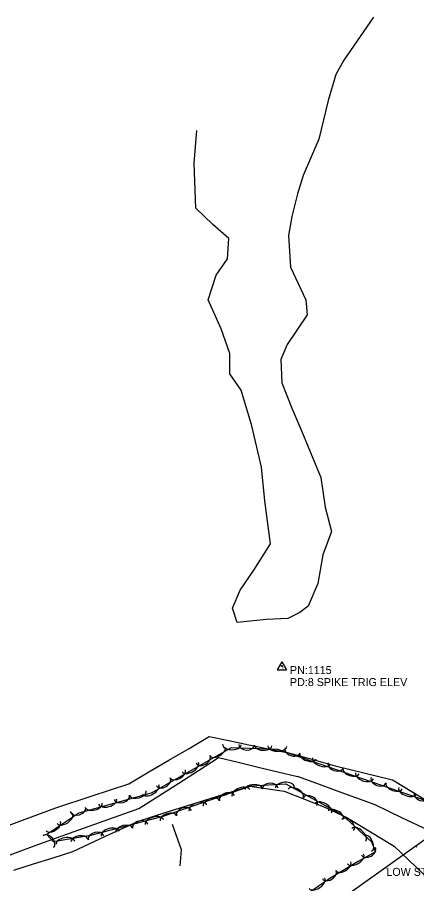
# Model space of a CAD drawing. Extents: x 1451369 to 1458940, y 1868647 to 1875095.
# Drawn here: x 1454031 to 1454280, y 1871459 to 1872000 of the extents above; entities that cross this region are included whole.
import ezdxf

# ---------------------------------------------------------------- set-up
doc = ezdxf.new("R2010")
doc.units = 0
for name, color, linetype in [('E_Existing_ROW', 7, 'Continuous'), ('E_Proposed ROW and Easements', 7, 'Continuous'), ('E_ROW Point Number', 7, 'Continuous'), ('E_Station Offset', 7, 'Continuous'), ('E_Tract Residual', 7, 'Continuous'), ('S_EXIST_ROW', 7, 'Continuous'), ('S_MISC_STRUCTURES_ANNOT', 7, 'Continuous'), ('S_SECONDARY_CTL_ANNOT', 7, 'Continuous')]:
    doc.layers.add(name, color=color, linetype=linetype)

msp = doc.modelspace()

# ---------------------------------------------------------------- linework, layer by layer
at = {"layer": 'E_Existing_ROW'}
msp.add_line((1454539.16, 1871667.36), (1454213.66, 1871435.13), dxfattribs=at)
at = {"layer": 'E_Proposed ROW and Easements'}
for points in [[(1454279.82, 1871481.69), (1454279.82, 1871481.74), (1454279.82, 1871481.69), (1454279.77, 1871481.69), (1454279.82, 1871481.69), (1454279.82, 1871481.64), (1454279.82, 1871481.69), (1454279.87, 1871481.69)], [(1454261.12, 1871468.48), (1454261.12, 1871468.53), (1454261.12, 1871468.48), (1454261.07, 1871468.48), (1454261.12, 1871468.48), (1454261.12, 1871468.43), (1454261.12, 1871468.48), (1454261.17, 1871468.48)]]:
    msp.add_lwpolyline(points, dxfattribs=at)
at = {"layer": 'E_ROW Point Number'}
msp.add_lwpolyline([(1454291.89, 1871508.3), (1454234.83, 1871528.11), (1454193.49, 1871542.37), (1454164.2, 1871543.4), (1454141.27, 1871530.42), (1454114.39, 1871515.17), (1454069.24, 1871502.63), (1454049.38, 1871489.36), (1454053.2, 1871485.02), (1454076.69, 1871488.85), (1454121.93, 1871500.68), (1454176.82, 1871519.68), (1454198.38, 1871520.85), (1454233.52, 1871501.66), (1454251.77, 1871484.69), (1454254.34, 1871478.55), (1454243.51, 1871472.47), (1454225.87, 1871461.79), (1454192.81, 1871439.12)], dxfattribs=at)
for centre, major_axis, ratio, start_param, end_param in [((1454155.79, 1871541.08), (4.65, 2.63), 0.540712, 3.141564, 6.283157), ((1454164.68, 1871545.5), (5.86, -0.21), 0.550067, 3.141587, 6.28318), ((1454173.94, 1871545.44), (4.95, -0.17), 0.685295, 3.141584, 6.283176), ((1454184.23, 1871544.82), (5.34, -0.19), 0.540687, 3.141587, 6.28318), ((1454193.09, 1871544.51), (5.86, -0.21), 0.550067, 3.141587, 6.28318), ((1454202.57, 1871541.76), (4.68, -1.62), 0.685295, 3.14157, 6.283163), ((1454146.7, 1871536.23), (4.31, 2.44), 0.685327, 3.141544, 6.283137), ((1454212.23, 1871538.15), (5.05, -1.74), 0.540687, 3.14158, 6.283172), ((1454220.61, 1871535.26), (5.55, -1.91), 0.550067, 3.141579, 6.283172), ((1454138.77, 1871531.44), (5.1, 2.9), 0.550074, 3.141593, 6.283185), ((1454229.45, 1871532.49), (4.68, -1.62), 0.685295, 3.14157, 6.283163), ((1454131.05, 1871527.07), (4.65, 2.64), 0.540694, 3.141593, 6.283185), ((1454239.1, 1871528.87), (5.05, -1.75), 0.540686, 3.141593, 6.283185), ((1454247.48, 1871525.97), (5.54, -1.92), 0.550066, 3.141593, 6.283185), ((1454114.04, 1871517.41), (5.1, 2.9), 0.550074, 3.141593, 6.283185), ((1454121.97, 1871522.21), (4.31, 2.45), 0.685304, 3.141593, 6.283185), ((1454178.29, 1871517.64), (-5.34, -0.29), 0.540688, 3.141593, 6.283185), ((1454188.59, 1871517.93), (-4.95, -0.27), 0.685296, 3.141593, 6.283185), ((1454197.82, 1871518.69), (-5.86, -0.32), 0.550068, 3.141593, 6.283185), ((1454256.31, 1871523.18), (4.68, -1.63), 0.685293, 3.141593, 6.283185), ((1454265.96, 1871519.55), (5.05, -1.75), 0.540686, 3.141593, 6.283185), ((1454106.05, 1871515.06), (5.15, 1.43), 0.54069, 3.141593, 6.283185), ((1454161.75, 1871511.95), (-4.68, -1.62), 0.6853, 3.141593, 6.283185), ((1454170.42, 1871515.22), (-5.55, -1.92), 0.550071, 3.141593, 6.283185), ((1454204.56, 1871515.06), (-4.69, 2.56), 0.540686, 3.141593, 6.283185), ((1454274.33, 1871516.64), (5.54, -1.92), 0.550066, 3.141593, 6.283185), ((1454283.17, 1871513.85), (4.68, -1.63), 0.685293, 3.141593, 6.283185), ((1454087.2, 1871509.82), (5.65, 1.57), 0.550071, 3.141593, 6.283185), ((1454096.06, 1871512.55), (4.77, 1.33), 0.685299, 3.141593, 6.283185), ((1454143.55, 1871505.92), (-5.55, -1.92), 0.550071, 3.141593, 6.283185), ((1454151.93, 1871508.82), (-5.05, -1.75), 0.540691, 3.141593, 6.283185), ((1454213.47, 1871509.89), (-4.35, 2.37), 0.685294, 3.141593, 6.283185), ((1454221.72, 1871505.69), (-5.15, 2.81), 0.550066, 3.141593, 6.283185), ((1454068.67, 1871504.94), (4.77, 1.33), 0.685299, 3.141593, 6.283185), ((1454078.66, 1871507.44), (5.15, 1.43), 0.54069, 3.141593, 6.283185), ((1454134.89, 1871502.64), (-4.68, -1.62), 0.6853, 3.141593, 6.283185), ((1454229.51, 1871501.44), (-4.69, 2.56), 0.540686, 3.141593, 6.283185), ((1454060.56, 1871499.38), (4.79, 3.2), 0.560424, 3.140937, 6.28253), ((1454116.39, 1871497.04), (-5.68, -1.48), 0.55007, 3.141593, 6.283185), ((1454125.07, 1871499.52), (-5.05, -1.75), 0.540691, 3.141593, 6.283185), ((1454236.94, 1871495.23), (-3.63, 3.37), 0.685296, 3.141593, 6.283185), ((1454053.32, 1871494.54), (4.36, 2.92), 0.550868, 3.140958, 6.282551), ((1454088.89, 1871489.85), (-5.68, -1.48), 0.55007, 3.141593, 6.283185), ((1454097.47, 1871492.09), (-5.17, -1.35), 0.54069, 3.141593, 6.283185), ((1454107.5, 1871494.44), (-4.79, -1.25), 0.685299, 3.141593, 6.283185), ((1454243.9, 1871489.11), (-4.3, 4), 0.550068, 3.141593, 6.283185), ((1454050.22, 1871484.8), (-3.22, 3.67), 0.695641, 3.143081, 6.284673), ((1454060.87, 1871484.12), (-5.79, -0.94), 0.550069, 3.141593, 6.283185), ((1454069.62, 1871485.55), (-5.28, -0.86), 0.540689, 3.141593, 6.283185), ((1454080, 1871487.25), (-4.79, -1.25), 0.685299, 3.141593, 6.283185), ((1454249.85, 1871483.78), (-2.07, 4.93), 0.540693, 3.141593, 6.283185), ((1454241.92, 1871473.98), (5.01, 3.03), 0.551082, 3.141802, 6.283395), ((1454249.91, 1871478.8), (4.32, 2.43), 0.685304, 3.141593, 6.283185), ((1454234.34, 1871469.4), (4.57, 2.76), 0.541684, 3.141795, 6.283388), ((1454225.41, 1871464.3), (4.23, 2.56), 0.686559, 3.141936, 6.283529), ((1454217.82, 1871458.85), (4.81, 3.3), 0.553457, 3.14195, 6.283543)]:
    msp.add_ellipse(centre, major_axis=major_axis, ratio=ratio, start_param=start_param, end_param=end_param, dxfattribs=at)
at = {"layer": 'E_Station Offset'}
for p, q in [((1454195.96, 1871597.1), (1454192.95, 1871592.15)), ((1454195.96, 1871597.1), (1454198.91, 1871592.15)), ((1454192.95, 1871592.15), (1454198.91, 1871592.15))]:
    msp.add_line(p, q, dxfattribs=at)
for radius in [0.311, 0.183, 0.103]:
    msp.add_circle((1454195.96, 1871594.49), radius, dxfattribs=at)
at = {"layer": 'E_Tract Residual'}
for points in [[(1454253.12, 1871999.62), (1454234.59, 1871972.88), (1454229.63, 1871963.93), (1454224.76, 1871947.65), (1454218.97, 1871923.45), (1454209.19, 1871900.79), (1454205.64, 1871889.48), (1454202.05, 1871875.28), (1454200.11, 1871863.38), (1454201.4, 1871843.58), (1454210.85, 1871823.15), (1454211.64, 1871813.77), (1454199.26, 1871795.26), (1454195.19, 1871785.93), (1454195.83, 1871771.37), (1454202.09, 1871755.49), (1454208.36, 1871740.9), (1454220.19, 1871712.18), (1454222.91, 1871693.64), (1454226.84, 1871678.47), (1454221.39, 1871663.94), (1454218.42, 1871646.14), (1454212.29, 1871631.88), (1454207.1, 1871628.03), (1454199.56, 1871624.12), (1454186.36, 1871623.52), (1454168.09, 1871621.61), (1454165.18, 1871630.74), (1454169.92, 1871641.86), (1454178.49, 1871654.37), (1454188.83, 1871670.88), (1454185.34, 1871697.6), (1454183.15, 1871718.63), (1454177.25, 1871744.44), (1454170.51, 1871766.74), (1454163.36, 1871776.93), (1454163.41, 1871789.62), (1454157.99, 1871805.19), (1454150.02, 1871823.19), (1454154.86, 1871838.52), (1454162.08, 1871848.87), (1454162.82, 1871861.52), (1454152.89, 1871870.34), (1454142.34, 1871880.37), (1454141.17, 1871908.45), (1454142.85, 1871928.93)], [(1454013.21, 1871490.57), (1454034.06, 1871498.26), (1454054.9, 1871505.94), (1454077.64, 1871513.48), (1454100.38, 1871521.02), (1454112.92, 1871528.38), (1454125.46, 1871535.74), (1454138, 1871543.1), (1454150.54, 1871550.46), (1454162.91, 1871547.92), (1454175.27, 1871545.38), (1454187.64, 1871542.84), (1454200.01, 1871540.3), (1454214.61, 1871536.27), (1454229.22, 1871532.25), (1454247.11, 1871527.9), (1454265, 1871523.55), (1454277.67, 1871515.79), (1454290.34, 1871508.04)], [(1454028.63, 1871467.06), (1454040.93, 1871470.94), (1454053.22, 1871474.82), (1454065.52, 1871478.7), (1454085.99, 1871488.2), (1454106.46, 1871497.71), (1454123.82, 1871503.18), (1454141.18, 1871508.64), (1454158.54, 1871514.11), (1454175.9, 1871519.57), (1454197.42, 1871516.47), (1454210.05, 1871511.39), (1454222.68, 1871506.3), (1454236.48, 1871500.02), (1454251.25, 1871491.03), (1454266.03, 1871482.04), (1454275.12, 1871473.27), (1454284.21, 1871464.5), (1454293.3, 1871455.74)]]:
    msp.add_lwpolyline(points, dxfattribs=at)
at = {"layer": 'S_EXIST_ROW'}
for points in [[(1453874.67, 1871403.94), (1453898.97, 1871408.04), (1453910.02, 1871415.94), (1453921.08, 1871423.84), (1453931.09, 1871437.12), (1453944.08, 1871453.49), (1453957.06, 1871469.87), (1453971.5, 1871480.54), (1453990.8, 1871484.27), (1454005.79, 1871479.41), (1454020.79, 1871474.55), (1454042.06, 1871482.37), (1454063.34, 1871490.19), (1454085, 1871497.84), (1454106.67, 1871505.5), (1454119.11, 1871513.46), (1454131.55, 1871521.42), (1454143.99, 1871529.38), (1454156.43, 1871537.34), (1454168.75, 1871534.39), (1454181.07, 1871531.43), (1454193.39, 1871528.48), (1454205.71, 1871525.52)], [(1454254.11, 1871507.84), (1454242.01, 1871512.26), (1454229.91, 1871516.68), (1454217.81, 1871521.1), (1454205.71, 1871525.52)], [(1454323.73, 1871469.69), (1454305.65, 1871480.74), (1454287.57, 1871491.78), (1454270.84, 1871499.81), (1454254.11, 1871507.84)], [(1454132.47, 1871469.82), (1454133.35, 1871479.64), (1454127.64, 1871495.46)]]:
    msp.add_lwpolyline(points, dxfattribs=at)

# ---------------------------------------------------------------- texts
at = {"layer": 'E_Station Offset'}
msp.add_text('TV', height=1.5, rotation=360, dxfattribs=at).set_placement((1454194.75, 1871592.48))
at = {"layer": 'S_MISC_STRUCTURES_ANNOT'}
msp.add_text('LOW STEEL', height=5, dxfattribs=at).set_placement((1454261.12, 1871463.48))
at = {"layer": 'S_SECONDARY_CTL_ANNOT'}
for s, p in [('PN:1115', (1454200.96, 1871589.49)), ('PD:8 SPIKE TRIG ELEV', (1454200.96, 1871581.99))]:
    msp.add_text(s, height=5, dxfattribs=at).set_placement(p)

doc.saveas('drawing.dxf')
